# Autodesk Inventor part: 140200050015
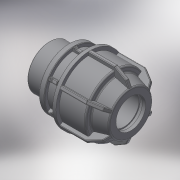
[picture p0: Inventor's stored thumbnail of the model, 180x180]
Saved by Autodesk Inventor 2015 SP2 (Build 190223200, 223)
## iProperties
Created: 2017-08
Part Number: 140200050015
Material: Generic
Description: PLASSON L.14 MALE ADAPTOR (SILVER) 50-1.1/2''
Document SubType Name: Modeling
Designer: KIM
Density: 1 g/cm^3
Appearance: Default
Author: KIM
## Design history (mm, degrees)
derived "140200.ipt"
feature "Solid1::140200.ipt"
tag "TaggingFeature1"
body "Solid1"
other parameters: "d4" = 15 deg, "d5" = 52.8, "d6" = 17.424, "d10" = 92, "d16" = 51, "d17" = 4, "d18" = 107, "d19" = 6.6, "d21" = 6.6, "d22" = 57.3636, "d24" = 4, "d25" = 82.8, "d26" = 69, "d27" = 4, "d28" = 135 deg, "d29" = 2.4, "d31" = 2.5, "d44" = 1, "d45" = 1.5, "d46" = 150 deg, "d49" = 4.6, "d50" = 0, "d51" = 2.76, "d52" = 1.84, "d53" = 45 deg, "d54" = 21, "d55" = 8.4, "d56" = 4.6, "d57" = 0, "d58" = 1.5, "d59" = 1, "d61" = 360 deg, "d63" = 47.803, "d65" = 22, "d66" = 64.53405, "R_" = 47.803, "E_" = 92, "H_" = 107, "l_2" = 22
